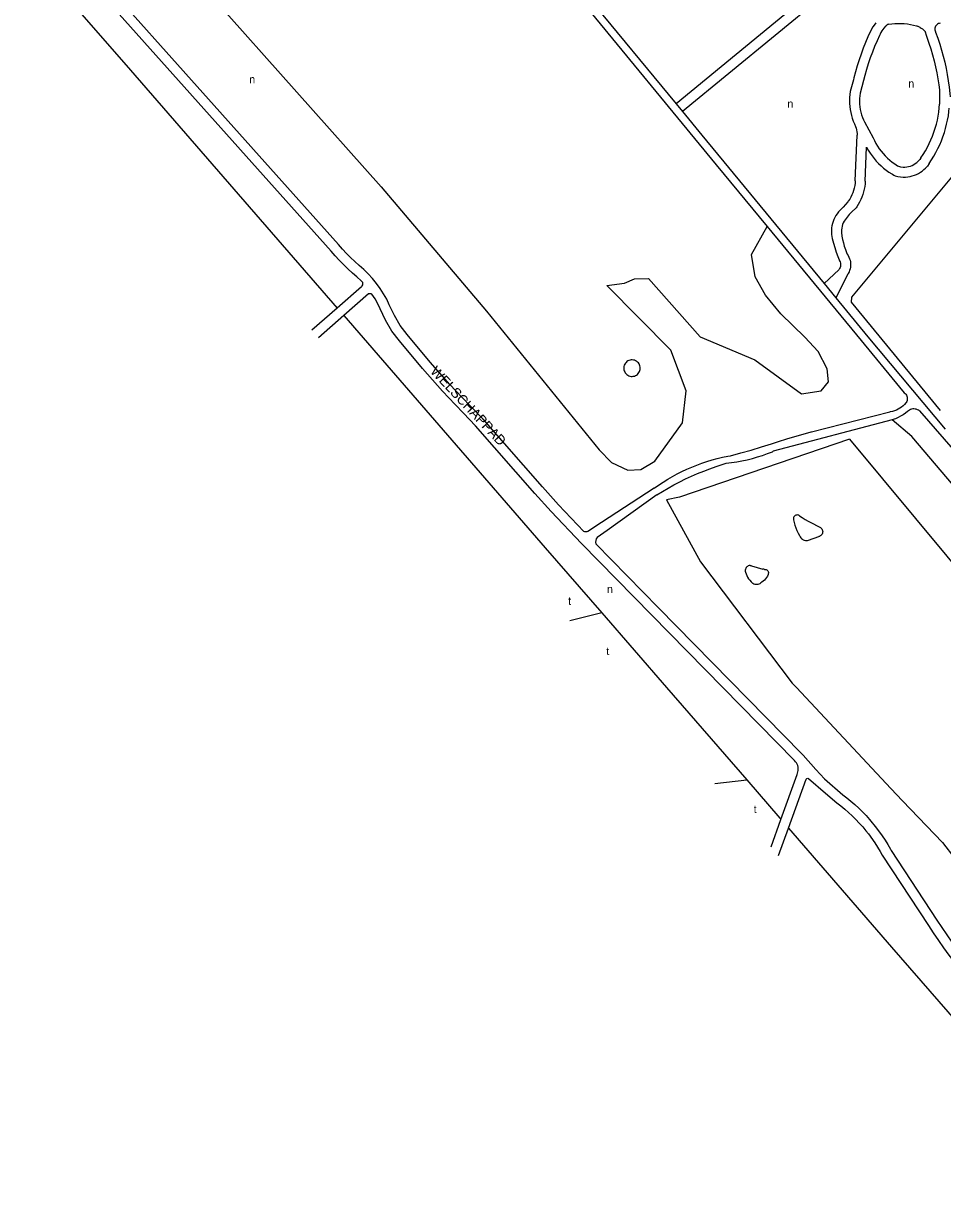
# Model space of a CAD drawing. Extents: x 156066 to 157805, y 383432 to 385631.
# Drawn here: x 156497 to 156957, y 384250 to 384832 of the extents above; entities that cross this region are included whole.
import ezdxf

# ---------------------------------------------------------------- set-up
doc = ezdxf.new("R2010")
doc.units = 0
for name, color, linetype in [('BLT_Basislijn', 7, 'Continuous'), ('BLT_Centroide', 7, 'Continuous'), ('BLT_Straatnaam', 7, 'Continuous'), ('BLT_Vlakafsluiter', 7, 'Continuous')]:
    doc.layers.add(name, color=color, linetype=linetype)

msp = doc.modelspace()

# ---------------------------------------------------------------- linework, layer by layer
at = {"layer": 'BLT_Basislijn'}
for p, q in [((156520.6, 384924.89), (156676.39, 384750.24)), ((156725.11, 384911.6), (156823.88, 384791.69)), ((156763.61, 384858.81), (156843.95, 384761.22)), ((156905.59, 384858.89), (156823.88, 384791.69)), ((156908.25, 384854.6), (156827.05, 384787.83)), ((156923.74, 384832.21), (156923.39, 384831.78)), ((156928.58, 384830.47), (156927.81, 384829.55)), ((156945.87, 384829.94), (156944.62, 384830.5)), ((156912.57, 384803.7), (156910.99, 384797.9)), ((156917.63, 384803.38), (156915.92, 384797.08)), ((156823.88, 384791.69), (156827.05, 384787.83)), ((156827.05, 384787.83), (156836.8, 384776)), ((156918.1, 384782.71), (156922.39, 384774.73)), ((156836.8, 384776), (156897.84, 384701.98)), ((156913.44, 384753.28), (156914.38, 384776.03)), ((156918.44, 384753.12), (156919.13, 384770.01)), ((156843.95, 384761.22), (156869.33, 384730.49)), ((156946.35, 384764.7), (156945.76, 384763.86)), ((156950.47, 384761.87), (156949.6, 384760.65)), ((156869.33, 384730.49), (156914.12, 384676.26)), ((156905.25, 384708.84), (156897.84, 384701.98)), ((156909.79, 384706.63), (156903.75, 384694.81)), ((156897.84, 384701.98), (156903.75, 384694.81)), ((156903.75, 384694.81), (156919.84, 384675.3)), ((156654.32, 384689.66), (156641.66, 384678.54)), ((156657.61, 384685.88), (156644.99, 384674.8)), ((156914.12, 384676.26), (156937.97, 384647.33)), ((156919.84, 384675.3), (156958.49, 384629.07)), ((156931.88, 384633.77), (156872.49, 384618.09)), ((156891.57, 384627.78), (156930.85, 384637.75)), ((156933, 384634.06), (156931.88, 384633.77)), ((156945.58, 384638.24), (157042.7, 384526.65)), ((156812.94, 384599.63), (156786.54, 384582.55)), ((156814.25, 384596.23), (156789.35, 384578.42)), ((156891.21, 384582.49), (156895.36, 384580.35)), ((156890.14, 384573.68), (156895.3, 384575.45)), ((156861.65, 384560.83), (156867.3, 384559.21)), ((156907.25, 384446.37), (156909.32, 384444.79)), ((156909.32, 384444.79), (156911.33, 384443.15)), ((156911.33, 384443.15), (156913.3, 384441.46)), ((156913.3, 384441.46), (156915.21, 384439.7)), ((156915.21, 384439.7), (156917.06, 384437.88)), ((156917.06, 384437.88), (156918.86, 384436.01)), ((156918.86, 384436.01), (156920.6, 384434.08)), ((156920.6, 384434.08), (156924.17, 384429.71)), ((156931.39, 384418.53), (156954.24, 384383.79)), ((156926.99, 384416.16), (156950.04, 384381.08))]:
    msp.add_line(p, q, dxfattribs=at)
for points in [[(156666.95, 384702.53), (156666.31, 384703.23), (156664.24, 384705.19), (156662.01, 384707.15), (156659.72, 384709.22), (156657.52, 384711.36), (156655.38, 384713.56), (156653.32, 384715.8), (156651.3, 384718.06), (156617.3, 384756.08), (156497.33, 384890.29)], [(156777.73, 384578), (156765.07, 384591.36), (156757.01, 384600.29), (156727.28, 384634.1), (156721.05, 384640.67), (156716.89, 384644.92), (156710.77, 384651.45), (156700.84, 384662.64), (156689.4, 384676.4), (156685.88, 384680.97), (156682.93, 384685.95), (156680.41, 384691.34), (156679.11, 384694.05), (156677.57, 384696.81), (156675.88, 384699.46), (156674.02, 384702.01), (156672.01, 384704.44), (156669.87, 384706.74), (156667.61, 384708.89), (156665.33, 384710.88), (156663.14, 384712.87), (156661.05, 384714.89), (156659.01, 384717), (156657.02, 384719.16), (156655.03, 384721.39), (156621.03, 384759.41), (156501.09, 384893.58)], [(156500, 384866.97), (156550.9, 384808.49), (156654.32, 384689.66)], [(156923.39, 384831.78), (156922.26, 384830.25), (156921.11, 384828.06)], [(156930.21, 384831.52), (156929.73, 384831.33), (156929.27, 384831.08), (156928.87, 384830.76), (156928.58, 384830.47)], [(156930.21, 384831.52), (156931.76, 384831.74), (156933.32, 384831.88), (156934.89, 384831.94), (156936.46, 384831.92), (156938.02, 384831.83), (156939.58, 384831.65), (156941.12, 384831.39), (156942.65, 384831.05), (156944.16, 384830.64), (156944.62, 384830.5)], [(156955.97, 384832.03), (156955.49, 384831.95), (156955.03, 384831.8), (156954.6, 384831.57), (156954.21, 384831.28), (156953.88, 384830.93), (156953.61, 384830.52), (156953.4, 384830.08), (156953.28, 384829.61), (156953.23, 384829.13), (156953.27, 384828.65), (156953.38, 384828.17), (156953.56, 384827.73), (156953.67, 384827.54)], [(156921.11, 384828.06), (156919.81, 384825.24), (156918.58, 384822.38), (156917.43, 384819.5), (156916.35, 384816.59), (156915.35, 384813.65), (156914.42, 384810.68), (156913.57, 384807.69), (156912.8, 384804.68), (156912.57, 384803.7)], [(156925.62, 384825.91), (156924.35, 384823.15), (156923.15, 384820.35), (156922.03, 384817.52), (156920.98, 384814.67), (156920, 384811.79), (156919.11, 384808.88), (156918.28, 384805.95), (156917.63, 384803.38)], [(156927.81, 384829.55), (156927.23, 384828.89), (156926.72, 384828.18), (156926.27, 384827.42), (156925.89, 384826.62), (156925.62, 384825.91)], [(156945.87, 384829.94), (156946.51, 384829.62), (156947.11, 384829.23), (156947.66, 384828.77), (156948.15, 384828.26), (156948.25, 384828.14)], [(156948.25, 384828.14), (156949.11, 384825.52), (156949.27, 384825.02)], [(156949.27, 384825.02), (156950.29, 384822.11), (156951.23, 384819.18), (156952.09, 384816.22), (156952.88, 384813.24), (156953.59, 384810.24), (156954.23, 384807.22), (156954.78, 384804.18), (156955.26, 384801.14), (156955.57, 384798.79)], [(156953.67, 384827.54), (156954.73, 384824.58), (156955.71, 384821.59), (156956.62, 384818.58), (156957.45, 384815.54), (156958.21, 384812.48), (156958.88, 384809.41), (156959.48, 384806.32), (156960, 384803.22), (156960.44, 384800.1), (156960.8, 384796.97), (156960.96, 384795.3)], [(156910.99, 384797.9), (156910.78, 384796.41), (156910.65, 384794.91), (156910.6, 384793.4), (156910.63, 384791.9), (156910.74, 384790.39), (156910.93, 384788.9), (156911.2, 384787.42), (156911.55, 384785.95), (156911.98, 384784.51), (156912.48, 384783.08), (156913.05, 384781.69), (156913.64, 384780.46)], [(156915.92, 384797.08), (156915.73, 384795.73), (156915.63, 384794.36), (156915.6, 384792.99), (156915.66, 384791.63), (156915.79, 384790.27), (156916, 384788.92), (156916.29, 384787.58), (156916.66, 384786.26), (156917.11, 384784.97), (156917.63, 384783.7), (156918.1, 384782.71)], [(156955.57, 384798.79), (156955.65, 384794.96), (156955.66, 384791.61)], [(156946.35, 384764.7), (156947.49, 384766.43), (156948.56, 384768.2), (156949.56, 384770.01), (156950.49, 384771.85), (156951.35, 384773.73), (156952.14, 384775.64), (156952.85, 384777.58), (156953.49, 384779.55), (156954.04, 384781.54), (156954.53, 384783.55), (156954.93, 384785.58), (156955.25, 384787.62), (156955.5, 384789.67), (156955.66, 384791.61)], [(156950.47, 384761.87), (156951.66, 384763.67), (156952.79, 384765.52), (156953.84, 384767.4), (156954.83, 384769.33), (156955.74, 384771.29), (156956.58, 384773.28), (156957.35, 384775.3), (156958.04, 384777.35), (156958.65, 384779.42), (156959.19, 384781.52), (156959.65, 384783.63), (156960.03, 384785.76), (156960.33, 384787.9), (156960.51, 384789.52)], [(156956.19, 384638.52), (156911.52, 384692.57), (156911.79, 384695.16), (156982.6, 384779.99)], [(156913.64, 384780.46), (156913.94, 384779.58), (156914.17, 384778.67), (156914.31, 384777.75), (156914.38, 384776.82), (156914.38, 384776.03)], [(156922.39, 384774.73), (156923.05, 384773.32), (156923.78, 384771.94), (156924.58, 384770.6), (156925.45, 384769.3), (156926.39, 384768.05), (156927.38, 384766.85), (156928.44, 384765.71), (156929.55, 384764.61), (156930.72, 384763.58), (156931.94, 384762.61), (156933.21, 384761.7), (156934.6, 384760.81)], [(156919.13, 384770.01), (156919.97, 384768.55), (156920.88, 384767.13), (156921.85, 384765.75), (156922.89, 384764.43), (156923.98, 384763.15), (156925.14, 384761.93), (156926.36, 384760.76), (156927.62, 384759.65), (156928.94, 384758.61), (156930.31, 384757.62), (156931.72, 384756.71), (156932.02, 384756.53)], [(156934.6, 384760.81), (156935.05, 384760.54), (156935.53, 384760.34), (156936.03, 384760.22), (156936.27, 384760.19)], [(156938.33, 384760.05), (156939.25, 384760.16), (156940.15, 384760.35), (156941.04, 384760.61), (156941.9, 384760.94), (156942.73, 384761.35), (156943.51, 384761.83), (156944.26, 384762.38), (156944.95, 384762.99), (156945.59, 384763.66), (156945.76, 384763.86)], [(156938.68, 384755.07), (156939.8, 384755.19), (156940.9, 384755.39), (156941.98, 384755.66), (156943.05, 384756.01), (156944.08, 384756.44), (156945.08, 384756.94), (156946.04, 384757.51), (156946.96, 384758.15), (156947.83, 384758.85), (156948.65, 384759.62), (156949.42, 384760.44), (156949.6, 384760.65)], [(156932.02, 384756.53), (156932.69, 384756.13), (156933.41, 384755.8), (156934.15, 384755.55), (156934.75, 384755.4)], [(156934.75, 384755.4), (156936.1, 384755.21), (156937.47, 384755.1), (156938.68, 384755.07)], [(156936.27, 384760.19), (156937.36, 384760.08), (156938.33, 384760.05)], [(156676.39, 384750.24), (156728.97, 384688.06), (156785.42, 384618.84), (156791.57, 384612.39), (156799.66, 384608.65), (156806.26, 384608.95), (156813.15, 384613.14), (156827.09, 384632.33), (156828.83, 384648.36), (156821.27, 384668.56), (156789.14, 384700.92), (156798.08, 384702.09), (156803.05, 384704.23), (156809.98, 384704.36), (156835.91, 384675.25), (156863.25, 384663.73), (156886.6, 384646.72), (156896.5, 384648.22), (156900.09, 384652.72), (156899.49, 384659.31), (156894.85, 384667.86), (156888.25, 384675.05), (156876.26, 384686.74), (156868.61, 384696.04), (156863.37, 384705.33), (156861.57, 384716.42), (156869.33, 384730.49)], [(156913.44, 384753.28), (156913.37, 384752.05), (156913.21, 384750.84), (156912.98, 384749.65), (156912.67, 384748.47), (156912.28, 384747.32), (156911.82, 384746.2), (156911.28, 384745.1), (156910.68, 384744.05), (156910, 384743.04), (156909.83, 384742.8)], [(156918.44, 384753.12), (156918.36, 384751.75), (156918.2, 384750.39), (156917.96, 384749.04), (156917.65, 384747.71), (156917.25, 384746.39), (156916.79, 384745.11), (156916.24, 384743.85), (156915.62, 384742.62), (156914.94, 384741.43), (156914.18, 384740.29), (156913.85, 384739.83)], [(156905.1, 384737.69), (156904.42, 384736.83), (156903.81, 384735.92), (156903.26, 384734.96), (156902.79, 384733.97), (156902.39, 384732.95), (156902.06, 384731.9), (156901.82, 384730.83), (156901.65, 384729.74), (156901.56, 384728.65), (156901.55, 384727.55), (156901.62, 384726.46), (156901.77, 384725.37), (156901.96, 384724.42)], [(156909.83, 384742.8), (156907.41, 384740.11), (156905.1, 384737.69)], [(156913.85, 384739.83), (156911.64, 384737.59), (156910.43, 384736.38), (156908.92, 384734.47)], [(156908.92, 384734.47), (156908.37, 384733.76), (156907.89, 384733), (156907.48, 384732.2), (156907.13, 384731.37), (156906.87, 384730.51), (156906.68, 384729.64), (156906.57, 384728.74), (156906.54, 384727.85), (156906.59, 384726.95), (156906.72, 384726.06), (156906.82, 384725.59)], [(156901.96, 384724.42), (156902.53, 384722.13), (156903.18, 384719.86), (156903.9, 384717.61), (156904.7, 384715.39), (156905.37, 384713.69)], [(156906.82, 384725.59), (156907.13, 384723.9), (156907.52, 384722.23), (156907.98, 384720.57), (156908.52, 384718.94), (156909.13, 384717.34), (156909.45, 384716.59)], [(156909.45, 384716.59), (156909.91, 384715.87), (156910.3, 384715.12), (156910.62, 384714.33), (156910.86, 384713.51), (156911.02, 384712.68), (156911.11, 384711.83), (156911.12, 384710.98), (156911.04, 384710.13), (156910.89, 384709.3), (156910.65, 384708.48), (156910.35, 384707.69), (156909.97, 384706.93), (156909.79, 384706.63)], [(156905.37, 384713.69), (156905.67, 384713.21), (156905.9, 384712.68), (156906.05, 384712.14), (156906.12, 384711.57), (156906.11, 384711), (156906.02, 384710.44), (156905.85, 384709.9), (156905.61, 384709.38), (156905.25, 384708.84)], [(156666.95, 384702.53), (156667.04, 384701.91), (156666.96, 384701.33), (156666.74, 384700.75), (156666.46, 384700.31), (156654.32, 384689.66)], [(156671.74, 384696.64), (156671.3, 384696.76), (156670.85, 384696.83), (156670.37, 384696.83), (156669.97, 384696.74), (156657.61, 384685.88)], [(156884.43, 384456.5), (156884.93, 384458.55), (156884.98, 384459.38), (156884.88, 384460.26), (156884.69, 384461), (156884.38, 384461.76), (156884.01, 384462.37), (156883.64, 384462.85), (156883.04, 384463.47), (156811.53, 384536.37), (156776.51, 384572.01), (156761.4, 384587.96), (156753.28, 384596.96), (156723.58, 384630.73), (156717.45, 384637.2), (156713.28, 384641.46), (156707.07, 384648.08), (156697.05, 384659.38), (156685.49, 384673.27), (156681.73, 384678.17), (156678.51, 384683.61), (156675.9, 384689.19), (156674.67, 384691.74), (156673.27, 384694.24), (156671.74, 384696.64)], [(156657.61, 384685.88), (156676.95, 384663.66)], [(156676.95, 384663.66), (156758.32, 384569.89), (156786.71, 384537.28)], [(156805.94, 384659.54), (156805.9, 384660.18), (156805.78, 384660.75), (156805.59, 384661.29), (156805.32, 384661.79), (156804.98, 384662.26), (156804.58, 384662.67), (156804.13, 384663.03), (156803.63, 384663.32), (156803.1, 384663.53), (156802.55, 384663.68), (156801.97, 384663.74), (156801.4, 384663.72), (156800.83, 384663.62), (156800.29, 384663.45), (156799.77, 384663.2), (156799.29, 384662.88), (156798.86, 384662.5), (156798.49, 384662.06), (156798.18, 384661.58), (156797.94, 384661.05), (156797.78, 384660.5), (156797.7, 384659.93), (156797.69, 384659.36), (156797.77, 384658.79), (156797.92, 384658.24), (156798.15, 384657.71), (156798.45, 384657.22), (156798.81, 384656.78), (156799.23, 384656.39), (156799.71, 384656.06), (156800.22, 384655.8), (156800.76, 384655.62), (156801.33, 384655.51), (156801.9, 384655.49), (156802.47, 384655.54), (156803.03, 384655.67), (156803.57, 384655.88), (156804.07, 384656.16), (156804.53, 384656.5), (156804.93, 384656.91), (156805.28, 384657.37), (156805.55, 384657.87), (156805.76, 384658.41), (156805.89, 384658.97), (156805.94, 384659.54)], [(156937.97, 384647.33), (156938.38, 384646.99), (156938.74, 384646.58), (156939.03, 384646.13), (156939.26, 384645.64), (156939.41, 384645.12), (156939.48, 384644.59), (156939.47, 384644.05), (156939.39, 384643.51), (156939.22, 384643), (156938.98, 384642.51), (156938.83, 384642.28)], [(156938.83, 384642.28), (156938.17, 384641.53), (156937.44, 384640.83), (156936.67, 384640.19), (156935.84, 384639.61), (156934.97, 384639.11), (156934.07, 384638.67), (156933.13, 384638.31), (156932.17, 384638.02), (156931.18, 384637.81), (156930.85, 384637.75)], [(156945.58, 384638.24), (156945.09, 384638.58), (156944.56, 384638.86), (156944, 384639.06), (156943.42, 384639.19), (156942.83, 384639.24), (156942.23, 384639.21), (156941.64, 384639.1), (156941.08, 384638.91), (156940.54, 384638.65), (156940.04, 384638.32), (156939.67, 384637.99)], [(157026.05, 384526.43), (156941.82, 384625.43), (156931.88, 384633.77)], [(156939.67, 384637.99), (156938.54, 384637.12), (156937.36, 384636.31), (156936.14, 384635.57), (156934.88, 384634.9), (156933.59, 384634.31), (156933, 384634.06)], [(156875.13, 384623.01), (156879.18, 384624.31), (156883.25, 384625.54), (156887.35, 384626.68), (156891.46, 384627.75), (156891.57, 384627.78)], [(156910.63, 384624.14), (156825.55, 384595.08), (156819, 384593.82), (156836.14, 384562.76), (156881.94, 384502.25), (156884.05, 384500)], [(156851.07, 384615.87), (156856.23, 384617.25), (156861.38, 384618.7), (156866.5, 384620.24), (156871.6, 384621.85), (156875.13, 384623.01)], [(156910.63, 384624.14), (156992.3, 384525.98), (157026.05, 384526.43)], [(156812.94, 384599.63), (156815.14, 384601.19), (156817.38, 384602.68), (156819.66, 384604.11), (156821.99, 384605.47), (156824.36, 384606.77), (156826.76, 384607.98), (156829.2, 384609.13), (156831.67, 384610.21), (156834.17, 384611.21), (156836.71, 384612.14), (156839.26, 384612.99), (156841.84, 384613.76), (156844.45, 384614.46), (156847.07, 384615.08), (156849.71, 384615.62), (156851.07, 384615.87)], [(156848.92, 384612.05), (156851.57, 384612.39), (156854.2, 384612.8), (156856.82, 384613.29), (156859.42, 384613.86), (156862.01, 384614.5), (156864.57, 384615.23), (156867.11, 384616.03), (156869.63, 384616.9), (156872.11, 384617.85), (156872.49, 384618.09)], [(156814.25, 384596.23), (156817.04, 384597.97), (156819.88, 384599.65), (156822.75, 384601.25), (156825.66, 384602.78), (156828.61, 384604.24), (156831.6, 384605.63), (156834.61, 384606.95), (156837.66, 384608.19), (156840.74, 384609.35), (156843.84, 384610.45), (156846.97, 384611.46), (156848.92, 384612.05)], [(156885.55, 384585.89), (156885.21, 384586.09), (156884.84, 384586.2), (156884.45, 384586.25), (156884.06, 384586.21), (156883.69, 384586.09), (156883.35, 384585.9), (156883.05, 384585.65), (156882.81, 384585.34), (156882.64, 384584.98), (156882.55, 384584.6), (156882.53, 384584.21), (156882.6, 384583.82)], [(156786.54, 384582.55), (156779.79, 384577.97), (156779.28, 384577.84), (156778.76, 384577.81), (156778.18, 384577.87), (156777.73, 384578)], [(156882.6, 384583.82), (156882.9, 384582.45), (156883.28, 384581.1), (156883.73, 384579.77), (156884.27, 384578.48), (156884.87, 384577.21), (156885.54, 384575.99), (156885.68, 384575.76)], [(156885.55, 384585.89), (156886.97, 384584.91), (156888.43, 384584), (156889.92, 384583.15), (156891.21, 384582.49)], [(156895.36, 384580.35), (156895.78, 384580.19), (156896.17, 384579.95), (156896.5, 384579.65), (156896.78, 384579.29), (156896.99, 384578.89), (156897.13, 384578.46), (156897.19, 384578.02), (156897.17, 384577.57), (156897.07, 384577.12), (156896.89, 384576.71), (156896.64, 384576.33), (156896.33, 384576), (156895.97, 384575.73), (156895.57, 384575.53), (156895.3, 384575.45)], [(156789.35, 384578.42), (156784.4, 384575.05), (156783.95, 384574.36), (156783.67, 384573.46), (156783.62, 384572.59), (156783.77, 384571.75)], [(156885.68, 384575.76), (156885.92, 384575.28), (156886.22, 384574.84), (156886.59, 384574.45), (156887.01, 384574.12), (156887.48, 384573.85), (156887.98, 384573.66), (156888.51, 384573.54), (156889.04, 384573.5), (156889.58, 384573.55), (156890.14, 384573.68)], [(156887.43, 384466.11), (156886.63, 384466.95), (156815.1, 384539.87), (156783.77, 384571.75)], [(156860.84, 384561.05), (156860.38, 384560.96), (156859.95, 384560.8), (156859.56, 384560.56), (156859.21, 384560.26), (156858.92, 384559.91), (156858.7, 384559.51), (156858.54, 384559.07), (156858.47, 384558.62), (156858.47, 384558.16), (156858.55, 384557.73)], [(156858.55, 384557.73), (156858.84, 384556.83), (156859.2, 384555.96), (156859.63, 384555.12), (156860.14, 384554.32), (156860.7, 384553.57), (156861.34, 384552.87), (156861.44, 384552.77)], [(156860.84, 384561.05), (156861.27, 384560.97), (156861.65, 384560.83)], [(156868.12, 384559.06), (156867.7, 384559.1), (156867.3, 384559.21)], [(156868.12, 384559.06), (156868.5, 384559.05), (156868.87, 384558.95), (156869.2, 384558.78), (156869.5, 384558.54), (156869.74, 384558.24), (156869.92, 384557.91), (156870.01, 384557.54), (156870.03, 384557.16), (156869.98, 384556.78), (156869.86, 384556.48)], [(156861.44, 384552.77), (156861.83, 384552.4), (156862.27, 384552.09), (156862.75, 384551.85), (156863.26, 384551.68), (156863.79, 384551.59), (156864.33, 384551.59), (156864.87, 384551.66), (156865.38, 384551.8), (156865.87, 384552.03), (156866.29, 384552.29)], [(156869.86, 384556.48), (156869.5, 384555.71), (156869.07, 384554.99), (156868.58, 384554.31), (156868.02, 384553.68), (156867.4, 384553.1), (156866.73, 384552.59), (156866.29, 384552.29)], [(156786.71, 384537.28), (156819.14, 384500)], [(156819.14, 384500), (156859.2, 384453.82)], [(156884.05, 384500), (156931.29, 384449.47), (156937.18, 384443.33)], [(156887.43, 384466.11), (156893.82, 384458.95), (156898.05, 384454.28), (156907.25, 384446.37)], [(156859.2, 384453.82), (156875.78, 384434.7)], [(156876.32, 384434.08), (156884.43, 384456.5)], [(156880.07, 384429.75), (156888.9, 384454.17), (156889.31, 384454.55), (156889.68, 384454.65), (156890.06, 384454.57)], [(156890.06, 384454.57), (156898.55, 384447.27)], [(156898.55, 384447.27), (156904.28, 384442.35)], [(156904.28, 384442.35), (156906.28, 384440.82), (156908.24, 384439.23), (156910.14, 384437.57), (156911.99, 384435.86), (156913.78, 384434.09), (156915.51, 384432.26), (156917.19, 384430.38), (156918.81, 384428.45), (156920.05, 384426.87)], [(156937.18, 384443.33), (156949.17, 384430.83)], [(156875.78, 384434.7), (156876.32, 384434.08)], [(156871.34, 384420.29), (156876.32, 384434.08)], [(156875.12, 384416.04), (156880.07, 384429.75)], [(156880.07, 384429.75), (156931.65, 384370.28), (157036.49, 384250)], [(156924.17, 384429.71), (156926.95, 384425.86), (156928.37, 384423.69), (156929.73, 384421.47), (156931.02, 384419.22), (156931.39, 384418.53)], [(156949.17, 384430.83), (156957.08, 384422.59), (156969.42, 384406.53)], [(156920.05, 384426.87), (156923.28, 384422.36), (156924.63, 384420.24), (156925.92, 384418.07), (156926.99, 384416.16)], [(156954.24, 384383.79), (156956.7, 384380.07), (156959.22, 384376.38), (156961.81, 384372.75), (156964.46, 384369.16), (156967.18, 384365.61), (156969.95, 384362.12), (156972.8, 384358.68), (156975.7, 384355.29), (156978.66, 384351.95), (156981.68, 384348.66), (156983.83, 384346.4)], [(156950.04, 384381.08), (156952.52, 384377.32), (156955.07, 384373.6), (156957.68, 384369.92), (156960.36, 384366.29), (156963.1, 384362.71), (156965.9, 384359.18), (156968.76, 384355.7), (156971.69, 384352.27), (156974.68, 384348.9), (156977.72, 384345.57), (156980.22, 384342.93)]]:
    msp.add_lwpolyline(points, dxfattribs=at)
at = {"layer": 'BLT_Vlakafsluiter'}
for p, q in [((156786.71, 384537.28), (156770.73, 384533.41)), ((156843.17, 384451.96), (156859.2, 384453.82))]:
    msp.add_line(p, q, dxfattribs=at)

# ---------------------------------------------------------------- texts
at = {"layer": 'BLT_Centroide'}
for s, p in [('n', (156610.34, 384801.97)), ('n', (156939.98, 384799.87)), ('n', (156879.51, 384789.79)), ('n', (156789.27, 384547.19)), ('t', (156769.85, 384541.28)), ('t', (156788.96, 384516.21)), ('t', (156862.67, 384437.26))]:
    msp.add_text(s, height=4, dxfattribs=at).set_placement(p)
at = {"layer": 'BLT_Straatnaam'}
msp.add_text('WELSCHAPPAD', height=5, rotation=313.19286, dxfattribs=at).set_placement((156700.59, 384657.73))

doc.saveas('drawing.dxf')
